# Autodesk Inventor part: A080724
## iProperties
Cutlength: 3.75
Material Desc: Pearson Desc
Material_Number: A077777
Author: Greg Purviance
Shininess: 25.0
PropertySet Name: _Private Model Information
Created: 2001-06
Part Number: A080724
User Status: NEW
Material: Steel, Mild
Description: Bushing,T-L,1215,0.750 B
Vendor: DODGE
Document SubType Name: Modeling
Designer: GAP
Control State: 0
Master: False
Checked Out: False
PropertySet Name: Design Tracking Control
Density: 0.0
Volumn: 0.0
Area: 0.0
PropertySet Name: Model Information
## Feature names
1. Extrusion2
2. Hole3
3. Hole4
4. Bore [Extrusion]
5. Key [Extrusion]
